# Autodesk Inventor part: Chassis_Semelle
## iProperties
Created: 2009-02
Part Number: Chassis_Semelle
Document SubType Name: Sheet Metal
Designer: claivier
Author: claivier
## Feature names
1. Perçage1 [Hole]
2. Miroir1 [Mirror]
3. Extrusion1
4. Extrusion2
5. Extrusion3
6. Plaque1
7. Pli1
8. Couper1
9. Couper2
